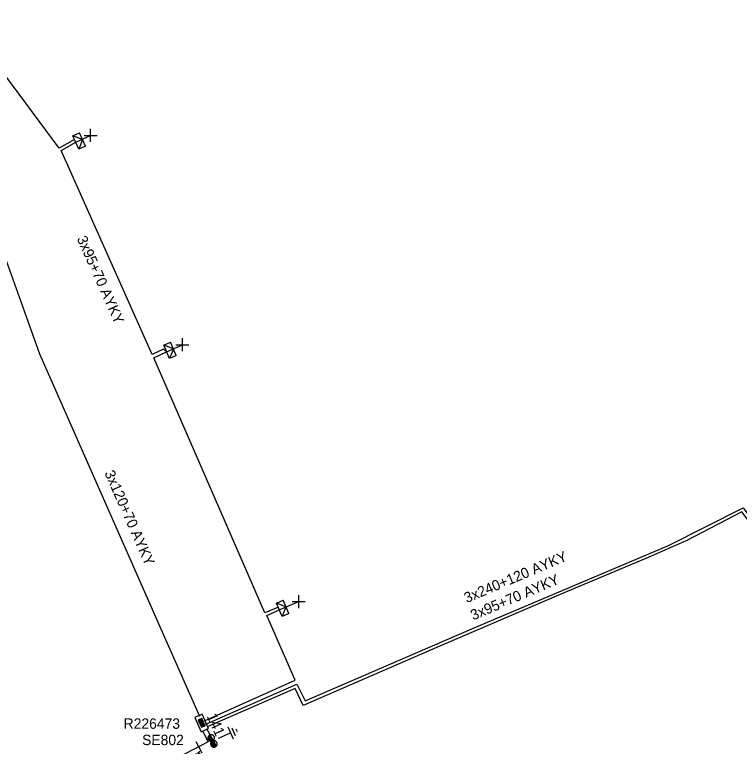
# Model space of a CAD drawing. Extents: x -544780 to -541582, y -1198995 to -1196551.
# Drawn here: x -542597.4 to -542527.7, y -1198687.9 to -1198617.5 of the extents above; entities that cross this region are included whole.
import ezdxf

# ---------------------------------------------------------------- set-up
doc = ezdxf.new("R2010")
doc.units = 0
for name, color, linetype in [('Vrstva 1', 7, 'Continuous'), ('Vrstva 13', 7, 'Continuous'), ('Vrstva 14', 7, 'Continuous'), ('Vrstva 15', 7, 'Continuous'), ('Vrstva 18', 7, 'Continuous'), ('Vrstva 2', 7, 'Continuous'), ('Vrstva 28', 7, 'Continuous'), ('Vrstva 29', 7, 'Continuous'), ('Vrstva 30', 7, 'Continuous'), ('Vrstva 31', 7, 'Continuous'), ('Vrstva 34', 7, 'Continuous'), ('Vrstva 5', 7, 'Continuous'), ('Vrstva 59', 7, 'Continuous'), ('Vrstva 6', 7, 'Continuous'), ('Vrstva 8', 7, 'Continuous'), ('Vrstva 9', 7, 'Continuous')]:
    doc.layers.add(name, color=color, linetype=linetype)

# ---------------------------------------------------------------- blocks, each defined once
blk = doc.blocks.new('NN450')
at = {"layer": 'Vrstva 2'}
for points in [[(0, 0), (0, 0.07), (-0.01, 0.13), (-0.03, 0.19), (-0.05, 0.25), (-0.08, 0.31), (-0.12, 0.37), (-0.16, 0.42), (-0.21, 0.46), (-0.26, 0.51), (-0.31, 0.54), (-0.37, 0.57), (-0.43, 0.59), (-0.5, 0.61), (-0.56, 0.62), (-0.63, 0.62), (-0.69, 0.62), (-0.75, 0.61), (-0.82, 0.59), (-0.88, 0.57), (-0.94, 0.54), (-0.99, 0.51), (-1.04, 0.46), (-1.09, 0.42), (-1.13, 0.37), (-1.17, 0.31), (-1.2, 0.25), (-1.22, 0.19), (-1.24, 0.13), (-1.25, 0.07), (-1.25, 0), (-1.25, -0.07), (-1.24, -0.13), (-1.22, -0.19), (-1.2, -0.25), (-1.17, -0.31), (-1.13, -0.37), (-1.09, -0.42), (-1.04, -0.46), (-0.99, -0.51), (-0.94, -0.54), (-0.88, -0.57), (-0.82, -0.59), (-0.75, -0.61), (-0.69, -0.62), (-0.62, -0.63), (-0.56, -0.62), (-0.5, -0.61), (-0.43, -0.59), (-0.37, -0.57), (-0.31, -0.54), (-0.26, -0.51), (-0.21, -0.46), (-0.16, -0.42), (-0.12, -0.37), (-0.08, -0.31), (-0.05, -0.25), (-0.03, -0.19), (-0.01, -0.13), (0, -0.07), (0, 0)], [(1.25, 0), (1.25, 0.07), (1.24, 0.13), (1.22, 0.19), (1.2, 0.25), (1.17, 0.31), (1.13, 0.37), (1.09, 0.42), (1.04, 0.46), (0.99, 0.51), (0.94, 0.54), (0.88, 0.57), (0.82, 0.59), (0.75, 0.61), (0.69, 0.62), (0.62, 0.62), (0.56, 0.62), (0.5, 0.61), (0.43, 0.59), (0.37, 0.57), (0.31, 0.54), (0.26, 0.51), (0.21, 0.46), (0.16, 0.42), (0.12, 0.37), (0.08, 0.31), (0.05, 0.25), (0.03, 0.19), (0.01, 0.13), (0, 0.07), (0, 0), (0, -0.07), (0.01, -0.13), (0.03, -0.19), (0.05, -0.25), (0.08, -0.31), (0.12, -0.37), (0.16, -0.42), (0.21, -0.46), (0.26, -0.51), (0.31, -0.54), (0.37, -0.57), (0.43, -0.59), (0.5, -0.61), (0.56, -0.62), (0.63, -0.63), (0.69, -0.62), (0.75, -0.61), (0.82, -0.59), (0.88, -0.57), (0.94, -0.54), (0.99, -0.51), (1.04, -0.46), (1.09, -0.42), (1.13, -0.37), (1.17, -0.31), (1.2, -0.25), (1.22, -0.19), (1.24, -0.13), (1.25, -0.07), (1.25, 0)], [(-1.25, 0), (1.25, 0)], [(-1.23, -0.16), (-0.02, -0.16)], [(-1.16, -0.32), (-0.09, -0.32)], [(-1.03, -0.47), (-0.22, -0.47)], [(0.02, -0.16), (1.23, -0.16)], [(0.09, -0.32), (1.16, -0.32)], [(0.22, -0.47), (1.03, -0.47)]]:
    blk.add_lwpolyline(points, dxfattribs=at)
blk = doc.blocks.new('NN840')
at = {"layer": 'Vrstva 15'}
for points in [[(0.003, 0.619), (0.003, -0.631)], [(-0.745, -0.71), (-0.745, -0.66)], [(-0.538, -0.385), (-0.538, -0.71)], [(-0.332, -0.385), (-0.332, -0.798)], [(-0.332, -0.641), (-0.125, -0.385)], [(-0.263, -0.557), (-0.091, -0.798)], [(-0.73, -0.764), (-0.745, -0.71)], [(-0.657, -0.798), (-0.73, -0.764)], [(-0.627, -0.798), (-0.657, -0.798)], [(-0.558, -0.764), (-0.627, -0.798)], [(-0.538, -0.71), (-0.558, -0.764)]]:
    blk.add_lwpolyline(points, dxfattribs=at)
blk = doc.blocks.new('NN800')
at = {"layer": 'Vrstva 1'}
for points in [[(-0.442, 0.442), (0.442, -0.442)], [(-0.442, -0.442), (0.442, 0.442)]]:
    blk.add_lwpolyline(points, dxfattribs=at)
blk = doc.blocks.new('NN620')
at = {"layer": 'Vrstva 8'}
for points in [[(0.752, 0.004), (-0.748, 0.004)], [(-0.748, 0.004), (-0.748, -0.746)], [(0.752, -0.746), (0.752, 0.004)], [(0.368, -0.18), (-0.376, -0.18)], [(-0.376, -0.18), (-0.376, -0.558)], [(-0.376, -0.558), (0.368, -0.558)], [(0.321, -0.227), (-0.329, -0.227)], [(-0.329, -0.227), (-0.329, -0.51)], [(-0.329, -0.51), (0.321, -0.51)], [(0.274, -0.274), (-0.281, -0.274)], [(-0.281, -0.274), (-0.281, -0.463)], [(-0.281, -0.463), (0.274, -0.463)], [(0.227, -0.321), (-0.234, -0.321)], [(-0.234, -0.321), (-0.234, -0.416)], [(-0.234, -0.416), (0.227, -0.416)], [(-0.193, -0.369), (0.185, -0.369)], [(0.227, -0.416), (0.227, -0.321)], [(0.274, -0.463), (0.274, -0.274)], [(0.321, -0.51), (0.321, -0.227)], [(0.368, -0.558), (0.368, -0.18)], [(-0.748, -0.746), (0.752, -0.746)]]:
    blk.add_lwpolyline(points, dxfattribs=at)
blk = doc.blocks.new('NN630')
at = {"layer": 'Vrstva 9'}
for points in [[(-0.003, -0.7), (-0.703, 0)], [(-0.703, -0.7), (-0.703, 0), (0.697, 0), (0.697, -0.7)], [(-0.703, -0.7), (0.697, -0.7)], [(-0.003, -0.7), (0.697, 0)]]:
    blk.add_lwpolyline(points, dxfattribs=at)
blk = doc.blocks.new('NN810')
at = {"layer": 'Vrstva 14'}
for points in [[(0.004, -0.64), (0.004, -1.89)], [(0.629, -1.89), (-0.621, -1.89)], [(0.388, -2.2), (-0.399, -2.2)], [(0.004, -2.515), (-0.124, -2.515)], [(0.137, -2.515), (0.004, -2.515)]]:
    blk.add_lwpolyline(points, dxfattribs=at)

msp = doc.modelspace()

# ---------------------------------------------------------------- linework, layer by layer
at = {"layer": 'Vrstva 1'}
msp.add_lwpolyline([(-542578.757, -1198687.477), (-542595.795, -1198696.34), (-542596.556, -1198696.737)], dxfattribs=at)
at = {"layer": 'Vrstva 5'}
for points in [[(-542603.643, -1198601.175), (-542603.643, -1198601.872), (-542606.417, -1198608.638), (-542600.333, -1198621.298), (-542602.878, -1198628.153), (-542594.994, -1198650.141), (-542582.826, -1198677.692), (-542579.598, -1198684.999)], [(-542579.113, -1198685.431), (-542570.374, -1198681.532), (-542573.106, -1198675.314), (-542571.913, -1198674.758), (-542571.988, -1198674.513), (-542573.292, -1198675.066), (-542583.97, -1198650.536), (-542582.75, -1198649.937), (-542583.039, -1198649.695), (-542584.156, -1198650.225), (-542592.91, -1198630.604), (-542591.487, -1198629.802), (-542591.606, -1198629.519), (-542593.096, -1198630.355), (-542600.174, -1198620.852), (-542605.947, -1198608.553), (-542603.251, -1198601.867), (-542603.29, -1198601.116)], [(-542578.966, -1198685.766), (-542570.236, -1198681.907), (-542569.426, -1198683.528), (-542553.163, -1198676.483), (-542534.47, -1198668.565), (-542527.273, -1198664.967), (-542523.721, -1198669.768), (-542518.512, -1198666.999), (-542515.21, -1198663.196), (-542511.534, -1198656.275), (-542505.116, -1198642.996), (-542501.502, -1198635.826), (-542484.115, -1198642.912)], [(-542484.091, -1198643.226), (-542501.366, -1198636.19), (-542506.975, -1198647.536), (-542509.303, -1198652.328), (-542500.017, -1198654.389), (-542500.092, -1198654.763), (-542509.425, -1198652.612), (-542511.568, -1198657.038), (-542515.009, -1198663.382), (-542518.317, -1198667.26), (-542519.983, -1198668.195), (-542523.438, -1198669.863), (-542507.961, -1198670.077), (-542507.952, -1198670.391), (-542523.804, -1198670.147), (-542527.421, -1198665.348), (-542532.713, -1198668.084), (-542536.648, -1198669.822), (-542544.202, -1198673.007), (-542556.615, -1198678.321), (-542569.621, -1198683.974), (-542570.394, -1198682.348), (-542578.86, -1198686.02)], [(-542579.301, -1198686.396), (-542578.757, -1198687.477)], [(-542578.932, -1198686.174), (-542577.967, -1198687.899)]]:
    msp.add_lwpolyline(points, dxfattribs=at)
at = {"layer": 'Vrstva 59'}
for points in [[(-542591.487, -1198629.802), (-542590.061, -1198629.133)], [(-542582.75, -1198649.937), (-542581.233, -1198649.268)], [(-542571.913, -1198674.758), (-542570.037, -1198673.966)]]:
    msp.add_lwpolyline(points, dxfattribs=at)

# ---------------------------------------------------------------- block references
at = {"layer": 'Vrstva 13', "xscale": 0.49999999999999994, "yscale": 0.5000000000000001, "rotation": -65.95058888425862}
msp.add_blockref('NN450', (-542578.336, -1198687.372), dxfattribs=at)
at = {"layer": 'Vrstva 15', "rotation": 114.04941111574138}
msp.add_blockref('NN810', (-542578.335, -1198687.372), dxfattribs=at)
at = {"layer": 'Vrstva 18', "rotation": 28.256686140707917}
msp.add_blockref('NN840', (-542579.665, -1198687.966), dxfattribs=at)
at = {"layer": 'Vrstva 28', "rotation": -65.95058882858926}
msp.add_blockref('NN620', (-542579.041, -1198685.502), dxfattribs=at)
at = {"layer": 'Vrstva 31'}
for p, rotation in [((-542591.487, -1198629.802), 113.30655000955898), ((-542582.75, -1198649.937), 113.3177083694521), ((-542571.913, -1198674.758), 113.480441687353)]:
    msp.add_blockref('NN630', p, dxfattribs=dict(at, rotation=rotation))
at = {"layer": 'Vrstva 34', "rotation": 45}
for p in [(-542590.061, -1198629.133), (-542581.233, -1198649.268), (-542570.037, -1198673.966)]:
    msp.add_blockref('NN800', p, dxfattribs=at)

# ---------------------------------------------------------------- texts
at = {"layer": 'Vrstva 14'}
msp.add_text('141', height=1, rotation=294.049, dxfattribs=at).set_placement((-542578.913, -1198684.986))
at = {"layer": 'Vrstva 29'}
msp.add_text('R226473', height=1, rotation=359.952, dxfattribs=at).set_placement((-542586.89, -1198686.206))
at = {"layer": 'Vrstva 30'}
msp.add_text('SE802', height=1, rotation=359.952, dxfattribs=at).set_placement((-542585.113, -1198687.778))
at = {"layer": 'Vrstva 6'}
for s, rotation, p in [('3x95+70 AYKY', 294.044, (-542591.417, -1198639.06)), ('3x120+70 AYKY', 293.829, (-542588.755, -1198661.601)), ('3x240+120 AYKY', 22.957, (-542553.878, -1198674.129)), ('3x95+70 AYKY', 23.176, (-542553.258, -1198675.794))]:
    msp.add_text(s, height=1, rotation=rotation, dxfattribs=at).set_placement(p)

doc.saveas('drawing.dxf')
